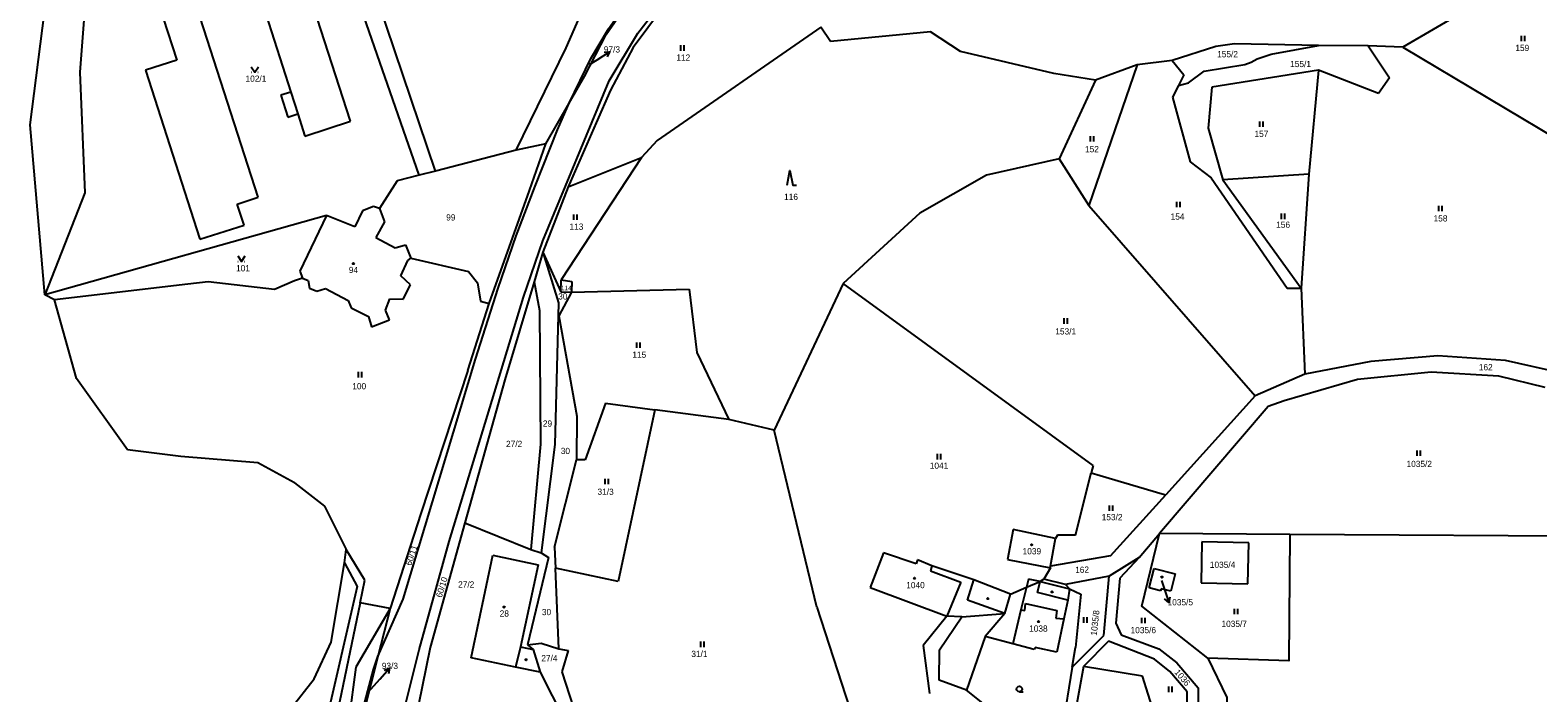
# Model space of a CAD drawing. Extents: x -670359 to -668019, y -978807 to -976674.
# Drawn here: x -670303.1 to -669891.1, y -977465.8 to -977284.7 of the extents above; entities that cross this region are included whole.
import ezdxf

# ---------------------------------------------------------------- set-up
doc = ezdxf.new("R2010")
doc.units = 0
for name, color, linetype in [('Hranice kat_území', 7, 'Continuous'), ('Hranice parcel', 7, 'Continuous'), ('Parcelní čísla', 7, 'Continuous'), ('Vnitřní kresba', 7, 'Continuous'), ('Značky budov', 7, 'Continuous'), ('Značky kultur', 7, 'Continuous')]:
    doc.layers.add(name, color=color, linetype=linetype)

msp = doc.modelspace()

# ---------------------------------------------------------------- linework, layer by layer
at = {"layer": 'Hranice kat_území'}
for points in [[(-670303.09, -977310.58), (-670295.8, -977253.36)], [(-670299.11, -977356.99), (-670303.09, -977310.58)], [(-670296.4, -977358.37), (-670299.11, -977356.99)], [(-670290.39, -977379.85), (-670296.4, -977358.37)], [(-670276.51, -977399.38), (-670290.39, -977379.85)], [(-670261.89, -977401.16), (-670276.51, -977399.38)], [(-670240.86, -977402.91), (-670261.89, -977401.16)], [(-670230.82, -977408.42), (-670240.86, -977402.91)], [(-670230.82, -977408.42), (-670222.62, -977414.79)], [(-670222.62, -977414.79), (-670216.78, -977426.59)], [(-670220.88, -977451.91), (-670217.21, -977430.27)], [(-670217.21, -977430.27), (-670216.78, -977426.59)], [(-670225.52, -977461.96), (-670220.88, -977451.91)], [(-670231.74, -977469.91), (-670225.52, -977461.96)]]:
    msp.add_lwpolyline(points, dxfattribs=at)
at = {"layer": 'Hranice parcel'}
for p, q in [((-670000.01, -977428.74), (-670005.31, -977434.42)), ((-670009.75, -977450.12), (-670008.29, -977433.88)), ((-670005.31, -977434.42), (-670006.43, -977446.74)), ((-670088.14, -977442.36), (-670079.11, -977470.1)), ((-670006.43, -977446.74), (-670004.98, -977449.96)), ((-670018.36, -977458.79), (-670009.75, -977450.12)), ((-670004.98, -977449.96), (-669994.72, -977453.76)), ((-670018.36, -977458.79), (-670017.48, -977453.41)), ((-670008.41, -977451.61), (-670015.27, -977458.55)), ((-669995.83, -977456.55), (-670008.41, -977451.61)), ((-669994.72, -977453.76), (-669989.76, -977457.53)), ((-670018.36, -977458.79), (-670022.83, -977486.05)), ((-669991.65, -977459.94), (-669995.83, -977456.55)), ((-669989.76, -977457.53), (-669983.91, -977464.41)), ((-669986.93, -977465.5), (-669991.65, -977459.94)), ((-669987.06, -977474.79), (-669986.93, -977465.5)), ((-669983.91, -977464.41), (-669984.06, -977475.2))]:
    msp.add_line(p, q, dxfattribs=at)
for points in [[(-670192.35, -977323.19), (-670223.53, -977230.71)], [(-670196.76, -977324.36), (-670228.36, -977233.44)], [(-670206.03, -977490.9), (-670201.37, -977472.26), (-670196.78, -977453.99), (-670188.6, -977424.41), (-670168.29, -977357.64), (-670162.97, -977342.22), (-670144.87, -977298.55), (-670137.06, -977285.54), (-670128.3, -977274.09), (-670118, -977262.95), (-670116.3, -977261.29)], [(-670215.56, -977309.6), (-670228.65, -977268.92)], [(-670155.78, -977304.6), (-670149.86, -977292.46), (-670145.08, -977284.34), (-670139.87, -977276.96), (-670134.89, -977270.75), (-670132.18, -977267.78)], [(-670122.33, -977267.85), (-670138.33, -977289.41)], [(-670241.01, -977273.11), (-670231.87, -977301.63)], [(-669899.87, -977272.82), (-669928.04, -977289.3)], [(-670145.67, -977285.92), (-670138.88, -977275.97)], [(-670266.7, -977281.45), (-670263.03, -977292.85)], [(-670240.8, -977330.34), (-670257.55, -977278.44)], [(-670151.59, -977297.32), (-670145.67, -977285.92)], [(-670087.08, -977283.85), (-670131.79, -977314.81)], [(-670084.43, -977287.79), (-670087.08, -977283.85)], [(-670057.09, -977285.13), (-670084.43, -977287.79)], [(-670048.87, -977290.52), (-670057.09, -977285.13)], [(-670138.33, -977289.41), (-670144.5, -977301.13)], [(-670023.39, -977296.58), (-670048.87, -977290.52)], [(-669979.14, -977289.2), (-669991.01, -977292.98)], [(-669989.31, -977299.81), (-669986.59, -977299.13), (-669982.28, -977295.87), (-669971.16, -977294.1), (-669969.41, -977293.48), (-669967.78, -977292.5), (-669963.95, -977291.28), (-669951.02, -977288.89)], [(-669974.03, -977288.45), (-669979.14, -977289.2)], [(-669951.02, -977288.89), (-669974.03, -977288.45)], [(-669937.48, -977288.95), (-669951.02, -977288.89)], [(-669937.48, -977288.95), (-669931.67, -977297.71)], [(-669928.04, -977289.3), (-669937.48, -977288.95)], [(-669928.04, -977289.3), (-669881.51, -977317.07)], [(-670263.03, -977292.85), (-670271.59, -977295.6)], [(-670000.63, -977294.13), (-670013.78, -977332.64)], [(-670000.63, -977294.13), (-670011.94, -977298.38)], [(-669991.01, -977292.98), (-670000.63, -977294.13)], [(-669991.01, -977292.98), (-669987.82, -977296.93)], [(-670271.59, -977295.6), (-670256.75, -977341.84)], [(-670155.78, -977304.6), (-670151.59, -977297.32)], [(-670011.94, -977298.38), (-670023.39, -977296.58)], [(-670011.94, -977298.38), (-670021.92, -977319.82)], [(-669987.82, -977296.93), (-669989.31, -977299.81)], [(-669951.04, -977295.59), (-669980.2, -977300.24)], [(-669951.04, -977295.59), (-669953.68, -977324.05)], [(-669934.61, -977301.96), (-669951.04, -977295.59)], [(-669931.67, -977297.71), (-669934.61, -977301.96)], [(-670231.87, -977301.63), (-670234.57, -977302.49)], [(-670234.57, -977302.49), (-670232.66, -977308.47)], [(-670144.5, -977301.13), (-670148.4, -977309.98)], [(-669989.31, -977299.81), (-669990.98, -977303.02)], [(-669980.2, -977300.24), (-669981.18, -977311.51)], [(-670201.12, -977440.18), (-670181.39, -977374.59), (-670175.18, -977355.21), (-670170.26, -977340.86), (-670165.11, -977327.29), (-670159.02, -977311.91), (-670155.78, -977304.6)], [(-670162.21, -977315.8), (-670155.78, -977304.6)], [(-669990.98, -977303.02), (-669986.09, -977320.65)], [(-670232.66, -977308.47), (-670229.95, -977307.6)], [(-670229.95, -977307.6), (-670228.02, -977313.62)], [(-670228.02, -977313.62), (-670215.56, -977309.6)], [(-670148.4, -977309.98), (-670156.05, -977327.52)], [(-670131.79, -977314.81), (-670136.07, -977319.5)], [(-669981.18, -977311.51), (-669977.19, -977325.55)], [(-670170.3, -977317.45), (-670192.35, -977323.19)], [(-670162.21, -977315.8), (-670170.3, -977317.45)], [(-670166.62, -977328.49), (-670162.21, -977315.8)], [(-670192.35, -977323.19), (-670196.76, -977324.36)], [(-670136.07, -977319.5), (-670157.98, -977352.9)], [(-670156.05, -977327.52), (-670136.07, -977319.5)], [(-670021.92, -977319.82), (-670041.73, -977324.34)], [(-670021.92, -977319.82), (-670013.78, -977332.64)], [(-669986.09, -977320.65), (-669980.39, -977325.01)], [(-670202.77, -977325.83), (-670207.63, -977333.4)], [(-670196.76, -977324.36), (-670202.77, -977325.83)], [(-670156.05, -977327.52), (-670162.98, -977345.39)], [(-670041.73, -977324.34), (-670059.99, -977334.68)], [(-669980.39, -977325.01), (-669959.59, -977355.17)], [(-669953.68, -977324.05), (-669977.19, -977325.55)], [(-669977.19, -977325.55), (-669955.76, -977355.15)], [(-669953.68, -977324.05), (-669955.76, -977355.15)], [(-670246.48, -977332.24), (-670240.8, -977330.34)], [(-670177.7, -977359.35), (-670166.62, -977328.49)], [(-670222.13, -977335.3), (-670299.11, -977356.99)], [(-670244.64, -977337.96), (-670246.48, -977332.24)], [(-670222.13, -977335.3), (-670229.44, -977350.52)], [(-670214.39, -977338.47), (-670222.13, -977335.3)], [(-670212.28, -977334.09), (-670214.39, -977338.47)], [(-670209.23, -977332.91), (-670212.28, -977334.09)], [(-670207.63, -977333.4), (-670209.23, -977332.91)], [(-670207.63, -977333.4), (-670206.3, -977337.09)], [(-670059.99, -977334.68), (-670080.94, -977353.88)], [(-670013.78, -977332.64), (-669968.39, -977384.63)], [(-670256.75, -977341.84), (-670244.64, -977337.96)], [(-670206.3, -977337.09), (-670208.65, -977341.31)], [(-670208.65, -977341.31), (-670203.31, -977344.15)], [(-670203.31, -977344.15), (-670200.5, -977343.37)], [(-670200.5, -977343.37), (-670199.08, -977346.97)], [(-670201.84, -977351.83), (-670199.85, -977347.6)], [(-670199.85, -977347.6), (-670199.08, -977346.97)], [(-670199.08, -977346.97), (-670183.27, -977350.68)], [(-670162.98, -977345.39), (-670165.4, -977353.5)], [(-670162.98, -977345.39), (-670158.68, -977359.17)], [(-670162.98, -977345.39), (-670158.11, -977356.19)], [(-670229.44, -977350.52), (-670228.7, -977352.45)], [(-670199.19, -977354.25), (-670201.84, -977351.83)], [(-670183.27, -977350.68), (-670180.89, -977353.74)], [(-670260.03, -977354.07), (-670296.4, -977358.37)], [(-670254.43, -977353.47), (-670260.03, -977354.07)], [(-670236.36, -977355.59), (-670254.43, -977353.47)], [(-670230.9, -977353.23), (-670236.36, -977355.59)], [(-670228.7, -977352.45), (-670230.9, -977353.23)], [(-670228.7, -977352.45), (-670227.14, -977353.1)], [(-670227.14, -977353.1), (-670226.75, -977355.18)], [(-670226.75, -977355.18), (-670224.76, -977355.99)], [(-670224.76, -977355.99), (-670222.43, -977355.29)], [(-670222.43, -977355.29), (-670216.21, -977358.53)], [(-670201.16, -977358.18), (-670199.19, -977354.25)], [(-670180.89, -977353.74), (-670180.04, -977358.78)], [(-670165.4, -977353.5), (-670173.4, -977380.26)], [(-670165.4, -977353.5), (-670163.9, -977361.3)], [(-670155.15, -977356.3), (-670158.63, -977362.77)], [(-670158.11, -977356.19), (-670157.98, -977352.9)], [(-670158.11, -977356.19), (-670155.15, -977356.3)], [(-670157.98, -977352.9), (-670155.03, -977353.34)], [(-670155.03, -977353.34), (-670155.15, -977356.3)], [(-670155.15, -977356.3), (-670123.04, -977355.5)], [(-670123.04, -977355.5), (-670120.93, -977372.79)], [(-670080.94, -977353.88), (-670099.79, -977393.97)], [(-670012.64, -977403.62), (-670080.94, -977353.88)], [(-669959.59, -977355.17), (-669955.76, -977355.15)], [(-669955.76, -977355.15), (-669954.75, -977378.72)], [(-670216.21, -977358.53), (-670215.35, -977360.54)], [(-670215.35, -977360.54), (-670210.64, -977362.97)], [(-670205.99, -977361.16), (-670204.77, -977358.13)], [(-670204.77, -977358.13), (-670201.16, -977358.18)], [(-670183.5, -977377.7), (-670177.7, -977359.35)], [(-670180.04, -977358.78), (-670177.7, -977359.35)], [(-670158.68, -977359.17), (-670159.68, -977397.88)], [(-670210.64, -977362.97), (-670209.78, -977365.77)], [(-670209.78, -977365.77), (-670204.89, -977363.81)], [(-670204.89, -977363.81), (-670205.99, -977361.16)], [(-670163.9, -977361.3), (-670163.6, -977397.85)], [(-670158.63, -977362.77), (-670153.7, -977390.16)], [(-670120.93, -977372.79), (-670112.18, -977391.09)], [(-669936.77, -977375.26), (-669954.75, -977378.72)], [(-669918.47, -977373.71), (-669936.77, -977375.26)], [(-669899.99, -977374.96), (-669918.47, -977373.71)], [(-669884.54, -977378.46), (-669899.99, -977374.96)], [(-670183.5, -977377.7), (-670196.38, -977416.73)], [(-670173.4, -977380.26), (-670184.32, -977419.3)], [(-669954.75, -977378.72), (-669968.39, -977384.63)], [(-669940.43, -977380.15), (-669960.39, -977385.94)], [(-669920.28, -977378.11), (-669940.43, -977380.15)], [(-669901.73, -977379.28), (-669920.28, -977378.11)], [(-669889.07, -977382.32), (-669901.73, -977379.28)], [(-669968.39, -977384.63), (-669992.8, -977411.69)], [(-670145.91, -977386.61), (-670151.47, -977402.09)], [(-670145.91, -977386.61), (-670132.35, -977388.41)], [(-670132.35, -977388.41), (-670142.37, -977435.34)], [(-670112.18, -977391.09), (-670132.35, -977388.41)], [(-669964.78, -977387.57), (-669994.46, -977422.25)], [(-669960.39, -977385.94), (-669964.78, -977387.57)], [(-670153.7, -977390.16), (-670153.79, -977402.08)], [(-670099.79, -977393.97), (-670112.18, -977391.09)], [(-670088.14, -977442.36), (-670099.79, -977393.97)], [(-670163.6, -977397.85), (-670166.29, -977426.62)], [(-670159.68, -977397.88), (-670163.49, -977427.52)], [(-670159.8, -977425.95), (-670153.79, -977402.08)], [(-670151.47, -977402.09), (-670153.79, -977402.08)], [(-670017.41, -977422.7), (-670013.15, -977405.65)], [(-670012.64, -977403.62), (-670013.15, -977405.65)], [(-670013.15, -977405.65), (-670010.72, -977406.37), (-669993.72, -977411.42), (-669992.8, -977411.69)], [(-670007.85, -977428.37), (-669992.8, -977411.69)], [(-670196.38, -977416.73), (-670204.73, -977442.75)], [(-670184.32, -977419.3), (-670193.77, -977453.38)], [(-670034.45, -977421.14), (-670036.03, -977429.37)], [(-670022.94, -977423.62), (-670034.45, -977421.14)], [(-670000.01, -977428.74), (-669994.46, -977422.25)], [(-669981.31, -977456.31), (-669999.34, -977442.1), (-669994.46, -977422.25)], [(-669958.87, -977422.47), (-669994.46, -977422.25)], [(-670159.8, -977425.95), (-670159.56, -977431.74)], [(-670024.28, -977431.13), (-670022.94, -977423.62)], [(-670022.38, -977422.67), (-670022.94, -977423.62)], [(-670017.41, -977422.7), (-670022.38, -977422.67)], [(-669982.9, -977424.54), (-669983.13, -977435.67)], [(-669970.1, -977424.8), (-669982.9, -977424.54)], [(-669958.87, -977422.47), (-669959.15, -977456.98), (-669981.31, -977456.31)], [(-669970.33, -977435.94), (-669970.1, -977424.8)], [(-669869.36, -977423.01), (-669958.87, -977422.47)], [(-670217.21, -977430.27), (-670213.73, -977436.69)], [(-670211.64, -977434.94), (-670216.78, -977426.59)], [(-670182.58, -977456.18), (-670176.62, -977428.15)], [(-670176.62, -977428.15), (-670164.24, -977430.8)], [(-670161.42, -977428.74), (-670167.19, -977452.69)], [(-670166.29, -977426.62), (-670163.49, -977427.52)], [(-670163.49, -977427.52), (-670161.42, -977428.74)], [(-670069.87, -977427.53), (-670073.53, -977436.95)], [(-670061, -977430.56), (-670069.87, -977427.53)], [(-670060.6, -977429.44), (-670061, -977430.56)], [(-670056.69, -977431.07), (-670060.6, -977429.44)], [(-670036.03, -977429.37), (-670024.28, -977431.61)], [(-670007.85, -977428.37), (-670024.28, -977431.13)], [(-670000.01, -977428.74), (-670008.29, -977433.88)], [(-670164.24, -977430.8), (-670169.12, -977453.16)], [(-670158.64, -977453.71), (-670159.56, -977431.74)], [(-670142.37, -977435.34), (-670159.56, -977431.74)], [(-670045.27, -977434.9), (-670056.69, -977431.07)], [(-670030.25, -977434.7), (-670030.81, -977436.93)], [(-670027.11, -977435.35), (-670030.25, -977434.7)], [(-670026.06, -977434.72), (-670027.11, -977435.35)], [(-670024.28, -977431.61), (-670026.06, -977434.72)], [(-670020.15, -977436.12), (-670026.06, -977434.72)], [(-670024.28, -977431.61), (-670024.28, -977431.13)], [(-670008.29, -977433.88), (-670020.15, -977436.12)], [(-669997.28, -977437.1), (-669995.94, -977431.82)], [(-669995.94, -977431.82), (-669990.21, -977433.27)], [(-669990.21, -977433.27), (-669991.41, -977437.97)], [(-670213.73, -977436.69), (-670222.65, -977475.42)], [(-670212.89, -977441.17), (-670211.64, -977434.94)], [(-670073.53, -977436.95), (-670052.62, -977444.85)], [(-670035.22, -977438.81), (-670045.27, -977434.9)], [(-670036.77, -977444.08), (-670035.22, -977438.81)], [(-670030.81, -977436.93), (-670032.37, -977443.07)], [(-670020.15, -977436.12), (-670019.12, -977437.33)], [(-670019.12, -977437.33), (-670019.54, -977440.44)], [(-670019.12, -977437.33), (-670016.01, -977438.79)], [(-670016.01, -977438.79), (-670017.48, -977453.41)], [(-669994.18, -977437.89), (-669997.28, -977437.1)], [(-669994.03, -977437.31), (-669994.18, -977437.89)], [(-669991.41, -977437.97), (-669994.03, -977437.31)], [(-669983.13, -977435.67), (-669970.33, -977435.94)], [(-670212.89, -977441.17), (-670220.34, -977477.03)], [(-670204.73, -977442.75), (-670212.89, -977441.17)], [(-670208.06, -977455.88), (-670201.12, -977440.18)], [(-670204.73, -977442.75), (-670208.06, -977455.88)], [(-670019.54, -977440.44), (-670020.62, -977445.55)], [(-670052.62, -977444.85), (-670059.08, -977452.8)], [(-670054.61, -977454.03), (-670048.54, -977445.04)], [(-670048.54, -977445.04), (-670052.62, -977444.85)], [(-670048.54, -977445.04), (-670036.77, -977444.08)], [(-670032.37, -977443.07), (-670034.59, -977452.33)], [(-670020.62, -977445.55), (-670022.53, -977454.66)], [(-670042.1, -977450.36), (-670047.21, -977465.04)], [(-670034.59, -977452.33), (-670042.1, -977450.36)], [(-670193.77, -977453.38), (-670198.08, -977474.39)], [(-670169.12, -977453.16), (-670165.68, -977453.9)], [(-670167.19, -977452.69), (-670163.43, -977452.16)], [(-670167.19, -977452.69), (-670165.68, -977453.9)], [(-670165.68, -977453.9), (-670163.73, -977460.15)], [(-670163.43, -977452.16), (-670158.64, -977453.71)], [(-670158.64, -977453.71), (-670156.08, -977454.21)], [(-670156.08, -977454.21), (-670157.8, -977460.03)], [(-670059.08, -977452.8), (-670057.31, -977465.91)], [(-670054.67, -977462.27), (-670054.61, -977454.03)], [(-670028.76, -977453.89), (-670034.59, -977452.33)], [(-670028.44, -977453.34), (-670028.76, -977453.89)], [(-670022.53, -977454.66), (-670028.44, -977453.34)], [(-670213.69, -977478.11), (-670213.16, -977474.17), (-670209.3, -977459.37), (-670208.06, -977455.88)], [(-670208.06, -977455.88), (-670213.69, -977478.11)], [(-670170.44, -977458.74), (-670182.58, -977456.18)], [(-670163.73, -977460.15), (-670170.44, -977458.74)], [(-670015.27, -977458.55), (-670020.69, -977488.66)], [(-669999.13, -977461.22), (-670015.27, -977458.55)], [(-669981.31, -977456.31), (-669976.1, -977467.06), (-669976.06, -977481.88)], [(-670163.73, -977460.15), (-670147.24, -977492.66)], [(-670157.8, -977460.03), (-670147.24, -977492.66)], [(-670047.21, -977465.04), (-670054.67, -977462.27)], [(-669989.82, -977490.72), (-669999.13, -977461.22)], [(-670037.86, -977472.47), (-670047.21, -977465.04)]]:
    msp.add_lwpolyline(points, dxfattribs=at)
at = {"layer": 'Parcelní čísla'}
for p, q in [((-670150.24, -977294.11), (-670148.15, -977292.79)), ((-670146.26, -977290.72), (-670144.76, -977290.66)), ((-669993.91, -977435.1), (-669993.2, -977437.3)), ((-669991.66, -977439.64), (-669991.97, -977441.11)), ((-670206.32, -977459.53), (-670204.89, -977459.06)), ((-670210.77, -977465.62), (-670207.56, -977462.04))]:
    msp.add_line(p, q, dxfattribs=at)
for points in [[(-670148.15, -977292.79), (-670144.76, -977290.66), (-670145.46, -977291.99)], [(-669993.2, -977437.3), (-669991.97, -977441.11), (-669993.09, -977440.1)], [(-670207.56, -977462.04), (-670204.89, -977459.06), (-670205.2, -977460.53)]]:
    msp.add_lwpolyline(points, dxfattribs=at)
at = {"layer": 'Vnitřní kresba'}
for points in [[(-670287.45, -977268.85), (-670289.49, -977296.13)], [(-670156.58, -977289.53), (-670149.5, -977273.26)], [(-670170.3, -977317.45), (-670156.58, -977289.53)], [(-670289.49, -977296.13), (-670288.11, -977329.15)], [(-670231.87, -977301.63), (-670229.95, -977307.6)], [(-670288.11, -977329.15), (-670299.11, -977356.99)], [(-670184.32, -977419.3), (-670166.29, -977426.62)], [(-670056.69, -977431.07), (-670057.1, -977432.42)], [(-670057.1, -977432.42), (-670048.8, -977435.52)], [(-670048.8, -977435.52), (-670052.62, -977444.85)], [(-670046.99, -977440.41), (-670045.27, -977434.9)], [(-670035.22, -977438.81), (-670030.81, -977436.93)], [(-670030.81, -977436.93), (-670027.11, -977435.35)], [(-670027.85, -977438.38), (-670027.11, -977435.35)], [(-670019.54, -977440.44), (-670027.85, -977438.38)], [(-670027.11, -977435.35), (-670019.12, -977437.33)], [(-670204.73, -977442.75), (-670214.13, -977458.76)], [(-670036.77, -977444.08), (-670046.99, -977440.41)], [(-670031.33, -977443.24), (-670031.07, -977441.32)], [(-670031.07, -977441.32), (-670022.52, -977443.3)], [(-670036.77, -977444.08), (-670042.1, -977450.36)], [(-670032.37, -977443.07), (-670031.33, -977443.24)], [(-670022.52, -977443.3), (-670022.78, -977445.38)], [(-670022.78, -977445.38), (-670020.62, -977445.55)], [(-670169.12, -977453.16), (-670170.44, -977458.74)], [(-670214.13, -977458.76), (-670216, -977473.14)]]:
    msp.add_lwpolyline(points, dxfattribs=at)
at = {"layer": 'Značky budov'}
for centre in [(-670214.77, -977348.47), (-670029.44, -977425.32), (-670061.43, -977434.45), (-669993.83, -977434.14), (-670173.58, -977442.33), (-670027.55, -977446.3)]:
    msp.add_circle(centre, 0.175, dxfattribs=at)
at = {"layer": 'Značky kultur'}
for p, q in [((-669895.63, -977286.23), (-669895.63, -977287.73)), ((-669894.63, -977287.73), (-669894.63, -977286.23)), ((-670125.37, -977288.84), (-670125.37, -977290.34)), ((-670124.37, -977290.34), (-670124.37, -977288.84)), ((-670242.64, -977296.2), (-670242.54, -977296.2)), ((-670240.84, -977296.2), (-670240.74, -977296.2)), ((-669967.17, -977309.63), (-669967.17, -977311.13)), ((-669966.17, -977311.13), (-669966.17, -977309.63)), ((-670013.48, -977313.63), (-670013.48, -977315.13)), ((-670012.48, -977315.13), (-670012.48, -977313.63)), ((-669989.84, -977331.59), (-669989.84, -977333.09)), ((-669988.84, -977333.09), (-669988.84, -977331.59)), ((-670154.58, -977335.04), (-670154.58, -977336.54)), ((-670153.58, -977336.54), (-670153.58, -977335.04)), ((-669961.22, -977334.82), (-669961.22, -977336.32)), ((-669960.22, -977336.32), (-669960.22, -977334.82)), ((-669918.24, -977332.67), (-669918.24, -977334.17)), ((-669917.24, -977334.17), (-669917.24, -977332.67)), ((-670246.32, -977347.89), (-670246.22, -977347.89)), ((-670244.52, -977347.89), (-670244.42, -977347.89)), ((-670020.59, -977363.43), (-670020.59, -977364.93)), ((-670019.59, -977364.93), (-670019.59, -977363.43)), ((-670137.4, -977370.02), (-670137.4, -977371.52)), ((-670136.4, -977371.52), (-670136.4, -977370.02)), ((-670213.45, -977378.06), (-670213.45, -977379.56)), ((-670212.45, -977379.56), (-670212.45, -977378.06)), ((-670055.21, -977400.5), (-670055.21, -977402)), ((-670054.21, -977402), (-670054.21, -977400.5)), ((-669924.21, -977399.53), (-669924.21, -977401.03)), ((-669923.21, -977401.03), (-669923.21, -977399.53)), ((-670146.1, -977407.29), (-670146.1, -977408.79)), ((-670145.1, -977408.79), (-670145.1, -977407.29)), ((-670008.24, -977414.54), (-670008.24, -977416.04)), ((-670007.24, -977416.04), (-670007.24, -977414.54)), ((-669974.12, -977442.81), (-669974.12, -977444.31)), ((-669973.12, -977444.31), (-669973.12, -977442.81)), ((-670015.3, -977445.11), (-670015.3, -977446.61)), ((-670014.3, -977446.61), (-670014.3, -977445.11)), ((-669999.43, -977445.27), (-669999.43, -977446.77)), ((-669998.43, -977446.77), (-669998.43, -977445.27)), ((-670119.91, -977451.78), (-670119.91, -977453.28)), ((-670118.91, -977453.28), (-670118.91, -977451.78)), ((-670032.78, -977465.47), (-670031.78, -977465.47)), ((-669992.05, -977464.04), (-669992.05, -977465.54)), ((-669991.05, -977465.54), (-669991.05, -977464.04))]:
    msp.add_line(p, q, dxfattribs=at)
for points in [[(-670242.69, -977294.7), (-670241.69, -977296.2), (-670240.69, -977294.7)], [(-670096.22, -977327.03), (-670095.47, -977323.03), (-670094.72, -977327.03), (-670093.72, -977327.03)], [(-670246.37, -977346.39), (-670245.37, -977347.89), (-670244.37, -977346.39)]]:
    msp.add_lwpolyline(points, dxfattribs=at)
for centre, radius in [((-670214.77, -977348.47), 0.175), ((-670029.44, -977425.32), 0.175), ((-670061.43, -977434.45), 0.175), ((-669993.83, -977434.14), 0.175), ((-670023.84, -977438.19), 0.175), ((-670173.58, -977442.33), 0.175), ((-670041.41, -977440.02), 0.175), ((-670027.55, -977446.3), 0.175), ((-670167.57, -977456.73), 0.175), ((-670032.78, -977464.72), 0.75)]:
    msp.add_circle(centre, radius, dxfattribs=at)

# ---------------------------------------------------------------- texts
at = {"layer": 'Parcelní čísla'}
for s, height, p in [('97/3', 1.7, (-670146.33, -977290.8)), ('155/2', 1.7, (-669978.74, -977292.1)), ('159', 1.7, (-669897.26, -977290.4)), ('97/3', 0.1, (-670150.4, -977294.11)), ('112', 1.7, (-670126.51, -977293.04)), ('155/1', 1.7, (-669958.79, -977294.79)), ('102/1', 1.7, (-670244.24, -977298.8)), ('157', 1.7, (-669968.55, -977313.89)), ('152', 1.7, (-670014.85, -977318.06)), ('116', 1.7, (-670097.08, -977331.08)), ('99', 1.7, (-670189.4, -977336.71)), ('154', 1.7, (-669991.45, -977336.47)), ('158', 1.7, (-669919.6, -977336.97)), ('113', 1.7, (-670155.72, -977339.24)), ('156', 1.7, (-669962.61, -977338.7)), ('101', 1.7, (-670246.83, -977350.59)), ('94', 1.7, (-670216.02, -977351.07)), ('114', 1.27, (-670158.04, -977355.78)), ('30', 1.7, (-670158.8, -977358.29)), ('153/1', 1.7, (-670022.97, -977367.85)), ('115', 1.7, (-670138.54, -977374.22)), ('162', 1.7, (-669907.24, -977377.65)), ('100', 1.7, (-670215.06, -977382.82)), ('29', 1.7, (-670163, -977393.04)), ('27/2', 1.7, (-670173.05, -977398.6)), ('30', 1.7, (-670158.1, -977400.52)), ('1041', 1.7, (-670057.27, -977404.55)), ('1035/2', 1.7, (-669926.99, -977404.07)), ('31/3', 1.7, (-670148.06, -977411.66)), ('153/2', 1.7, (-670010.29, -977418.6)), ('1039', 1.7, (-670031.9, -977427.92)), ('1035/4', 1.7, (-669980.74, -977431.61)), ('27/2', 1.7, (-670186.14, -977436.99)), ('1040', 1.7, (-670063.7, -977437.17)), ('1035/5', 0.1, (-669993.91, -977435.1)), ('30', 1.7, (-670163.26, -977444.54)), ('1035/5', 1.7, (-669992.29, -977441.86)), ('28', 1.7, (-670174.79, -977444.93)), ('1035/7', 1.7, (-669977.56, -977447.76)), ('1038', 1.7, (-670030.12, -977449.05)), ('1035/6', 1.7, (-670002.4, -977449.47)), ('31/1', 1.7, (-670122.42, -977455.97)), ('93/3', 1.7, (-670207, -977459.25)), ('27/4', 1.7, (-670163.41, -977457.14)), ('93/3', 0.1, (-670210.93, -977465.62))]:
    msp.add_text(s, height=height, dxfattribs=at).set_placement(p)
for s, rotation, p in [('60/11', 71.231, (-670198.98, -977431.16)), ('60/10', 73.1498, (-670190.63, -977439.88)), ('162', 1.8553, (-670017.52, -977433.05)), ('1035/8', 83.7, (-670011.64, -977450.19)), ('1036', 310.5, (-669990.52, -977460.23))]:
    msp.add_text(s, height=1.7, rotation=rotation, dxfattribs=at).set_placement(p)

doc.saveas('drawing.dxf')
